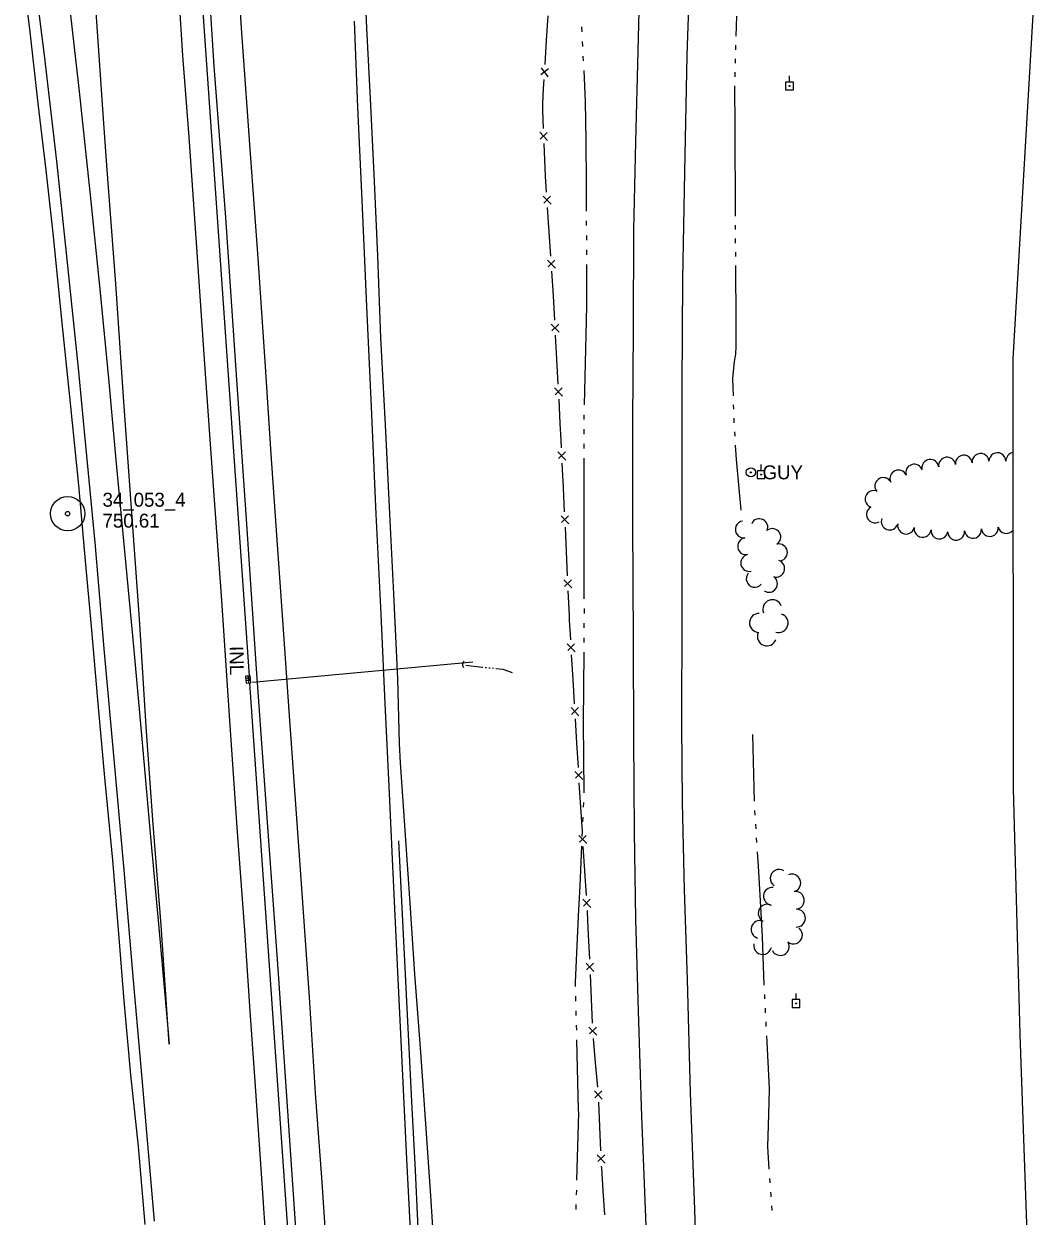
# Model space of a CAD drawing. Extents: x 589250 to 1188077, y 162953 to 363065.
# Drawn here: x 594002 to 594438, y 172738 to 173250 of the extents above; entities that cross this region are included whole.
import ezdxf

# ---------------------------------------------------------------- set-up
doc = ezdxf.new("R2010")
doc.units = 0
for name, color, linetype in [('E_DRN', 7, 'Continuous'), ('E_DRN_Pipe', 7, 'Continuous'), ('E_DRN_SS_UG', 7, 'Continuous'), ('E_DRN_Text', 7, 'Continuous'), ('E_FEN_P', 7, 'Continuous'), ('E_LAND_TreeLine_P', 7, 'Continuous'), ('E_MAP_Limits', 7, 'Continuous'), ('E_MAP_PassPoints', 7, 'Continuous'), ('E_RDWY', 7, 'Continuous'), ('E_RDWY_Gravel', 7, 'Continuous'), ('E_UTL_EGuyWire', 7, 'Continuous'), ('E_UTL_EPowerPole', 7, 'Continuous'), ('E_WAL', 7, 'Continuous'), ('E_WTR_FlowLine', 7, 'Continuous')]:
    doc.layers.add(name, color=color, linetype=linetype)

msp = doc.modelspace()

# ---------------------------------------------------------------- linework, layer by layer
at = {"layer": 'E_DRN'}
for p, q in [((594099.38, 172970.2), (594097.39, 172970.05)), ((594097.39, 172970.05), (594097.61, 172967.06)), ((594099.46, 172969.2), (594097.46, 172969.06)), ((594099.53, 172968.21), (594097.54, 172968.06)), ((594097.61, 172967.06), (594099.6, 172967.21)), ((594098.38, 172970.13), (594098.61, 172967.14)), ((594099.6, 172967.21), (594099.38, 172970.2))]:
    msp.add_line(p, q, dxfattribs=at)
msp.add_arc((594192.42, 172975.03), 1.75, 124.0117, 230.2719, dxfattribs=at)
at = {"layer": 'E_DRN_Pipe'}
msp.add_line((594117.95, 172698.49), (594099.27, 172967.03), dxfattribs=at)
msp.add_lwpolyline([(594163.21, 172899.17), (594166.48, 172833.15), (594167.75, 172807.22), (594168.84, 172784.41), (594170.33, 172757.55), (594171.64, 172729.6), (594173.17, 172701.66), (594174.76, 172674.39), (594177.1, 172640.49), (594178.95, 172611.66), (594181.35, 172577.92), (594185.75, 172513.06), (594188.07, 172482.37), (594189.42, 172460.9)], dxfattribs=at)
at = {"layer": 'E_DRN_SS_UG'}
msp.add_line((594099.21, 172967.94), (594078.59, 173264.28), dxfattribs=at)
msp.add_lwpolyline([(594100.33, 172967.49), (594195.15, 172976.11)], dxfattribs=at)
at = {"layer": 'E_FEN_P'}
for p, q in [((594227.4, 173253.92), (594226.71, 173243.44)), ((594226.71, 173243.44), (594226.02, 173232.95)), ((594227.62, 173231.06), (594224.32, 173228.52)), ((594224.45, 173231.44), (594227.39, 173227.58)), ((594225.35, 173222.69), (594225.14, 173215.97)), ((594225.6, 173226.46), (594225.35, 173222.69)), ((594225.14, 173215.97), (594225.05, 173212.98)), ((594225.05, 173212.98), (594225.36, 173205.47)), ((594223.95, 173203.79), (594227.29, 173200.27)), ((594227.15, 173203.76), (594224.14, 173200.88)), ((594225.63, 173198.97), (594226.06, 173188.47)), ((594226.06, 173188.47), (594226.21, 173184.79)), ((594226.21, 173184.79), (594226.68, 173177.99)), ((594225.32, 173176.27), (594228.75, 173172.84)), ((594228.51, 173176.32), (594225.58, 173173.36)), ((594227.12, 173171.5), (594227.84, 173161.01)), ((594227.84, 173161.01), (594228.55, 173150.53)), ((594227.2, 173148.82), (594230.63, 173145.38)), ((594230.39, 173148.87), (594227.46, 173145.91)), ((594229, 173144.04), (594229.57, 173135.61)), ((594229.57, 173135.61), (594229.68, 173133.56)), ((594229.68, 173133.56), (594230.24, 173123.07)), ((594228.85, 173121.37), (594232.23, 173117.89)), ((594232.04, 173121.37), (594229.07, 173118.46)), ((594230.58, 173116.57), (594231.13, 173106.08)), ((594231.13, 173106.08), (594231.68, 173095.59)), ((594230.3, 173093.89), (594233.67, 173090.41)), ((594233.49, 173093.89), (594230.52, 173090.98)), ((594232.03, 173089.09), (594232.58, 173078.6)), ((594232.58, 173078.6), (594232.96, 173071.4)), ((594232.96, 173071.4), (594233.12, 173068.11)), ((594231.73, 173066.42), (594235.09, 173062.92)), ((594234.92, 173066.41), (594231.93, 173063.51)), ((594233.43, 173061.61), (594233.94, 173051.11)), ((594233.94, 173051.11), (594234.45, 173040.62)), ((594233.06, 173038.93), (594236.42, 173035.43)), ((594236.25, 173038.92), (594233.27, 173036.02)), ((594234.76, 173034.12), (594235.23, 173023.63)), ((594235.23, 173023.63), (594235.7, 173013.13)), ((594234.31, 173011.45), (594237.65, 173007.94)), ((594237.5, 173011.43), (594234.5, 173008.53)), ((594236, 173006.63), (594236.47, 172996.14)), ((594236.47, 172996.14), (594236.56, 172994.02)), ((594236.56, 172994.02), (594237.06, 172985.65)), ((594235.69, 172983.95), (594239.09, 172980.48)), ((594238.88, 172983.97), (594235.93, 172981.03)), ((594237.45, 172979.15), (594238.07, 172968.67)), ((594238.07, 172968.67), (594238.7, 172958.18)), ((594237.33, 172956.48), (594240.73, 172953.01)), ((594240.52, 172956.5), (594237.57, 172953.56)), ((594239.09, 172951.69), (594239.71, 172941.2)), ((594239.71, 172941.2), (594240.34, 172930.71)), ((594238.97, 172929.01), (594242.37, 172925.54)), ((594242.16, 172929.03), (594239.21, 172926.1)), ((594240.73, 172924.22), (594241.39, 172913.73)), ((594241.39, 172913.73), (594242.06, 172903.25)), ((594240.69, 172901.54), (594244.1, 172898.09)), ((594243.88, 172901.57), (594240.94, 172898.63)), ((594242.47, 172896.75), (594243.14, 172886.27)), ((594243.14, 172886.27), (594243.8, 172875.78)), ((594242.43, 172874.08), (594245.85, 172870.63)), ((594245.63, 172874.11), (594242.68, 172871.16)), ((594244.21, 172869.29), (594244.49, 172864.88)), ((594244.49, 172864.88), (594244.76, 172858.8)), ((594244.76, 172858.8), (594245.23, 172848.3)), ((594243.83, 172846.62), (594247.18, 172843.11)), ((594247.02, 172846.6), (594244.03, 172843.71)), ((594245.52, 172841.81), (594245.99, 172831.31)), ((594245.99, 172831.31), (594246.46, 172820.81)), ((594245.06, 172819.13), (594248.41, 172815.62)), ((594248.25, 172819.11), (594245.26, 172816.22)), ((594246.87, 172814.32), (594247.78, 172803.85)), ((594247.78, 172803.85), (594248.68, 172793.39)), ((594247.39, 172791.71), (594250.74, 172788.2)), ((594250.58, 172791.69), (594247.59, 172788.8)), ((594249.08, 172786.9), (594249.56, 172776.4)), ((594249.56, 172776.4), (594250.04, 172765.9)), ((594248.64, 172764.22), (594251.99, 172760.71)), ((594251.83, 172764.2), (594248.84, 172761.31)), ((594250.33, 172759.41), (594250.37, 172758.63)), ((594250.37, 172758.63), (594251.02, 172748.92)), ((594251.02, 172748.92), (594251.73, 172738.44))]:
    msp.add_line(p, q, dxfattribs=at)
at = {"layer": 'E_LAND_TreeLine_P'}
for centre, radius, start, end in [((594391.82, 173059.55), 3.63, 7.4389, 187.4389), ((594399.01, 173060.49), 3.63, 7.4389, 187.4389), ((594406.21, 173061.35), 3.63, 5.9256, 185.9256), ((594413.43, 173062.1), 3.63, 5.9256, 185.9256), ((594420.67, 173062.42), 3.63, 0.9559, 180.9559), ((594427.93, 173062.54), 3.63, 98.8023, 180.9559), ((594378.09, 173054.96), 3.63, 25.1014, 205.1014), ((594384.88, 173057.47), 3.63, 18.0586, 198.0586), ((594371.62, 173051.72), 3.63, 39.1131, 219.1131), ((594367.42, 173046.16), 3.63, 71.7769, 251.7769), ((594368.04, 173039.54), 3.63, 119.0284, 299.0284), ((594318.31, 173034.02), 3.64, 335.1349, 155.1349), ((594374.38, 173036.5), 3.63, 160.1836, 340.1836), ((594311.61, 173033.07), 3.64, 97.7986, 277.7986), ((594323.9, 173029.8), 3.64, 301.9196, 121.9196), ((594381.4, 173034.73), 3.63, 168.5751, 348.5751), ((594388.51, 173033.34), 3.63, 173.9748, 353.9748), ((594395.73, 173032.58), 3.63, 173.9748, 353.9748), ((594402.94, 173032.11), 3.63, 186.3117, 6.3117), ((594410.15, 173032.91), 3.63, 186.3117, 6.3117), ((594417.37, 173033.71), 3.63, 186.3117, 6.3117), ((594424.5, 173034.98), 3.63, 191.495, 322.668), ((594312.6, 173025.85), 3.64, 97.7986, 277.7986), ((594326.73, 173023.21), 3.64, 281.4473, 101.4473), ((594313.97, 173018.7), 3.64, 102.548, 282.548), ((594325.56, 173016.24), 3.64, 250.8606, 70.8606), ((594316.33, 173011.88), 3.64, 139.5322, 319.5322), ((594322.46, 173009.7), 3.64, 235.4182, 55.4182), ((594323.91, 172998.76), 4.1, 21.5119, 201.5119), ((594318.18, 172992.91), 4.1, 88.5699, 268.5699), ((594326.57, 172992.81), 4.1, 252.5209, 72.5209), ((594321.56, 172987.12), 4.1, 159.1545, 339.1545), ((594326.82, 172883.12), 3.83, 57.2658, 237.2658), ((594332.27, 172881.1), 3.83, 291.1807, 111.1807), ((594323.96, 172875.41), 3.83, 84.6157, 264.6157), ((594333.8, 172873.63), 3.83, 277.126, 97.126), ((594321.65, 172868.13), 3.83, 64.3908, 244.3908), ((594334.26, 172866), 3.83, 267.5894, 87.5894), ((594318.61, 172861.1), 3.83, 72.5209, 252.5209), ((594333.01, 172858.7), 3.83, 229.5322, 49.5322), ((594319.74, 172854.2), 3.83, 167.9612, 347.9612), ((594327.29, 172853.81), 3.83, 207.5209, 27.5209)]:
    msp.add_arc(centre, radius, start, end, dxfattribs=at)
at = {"layer": 'E_MAP_Limits'}
for p, q in [((594437.75, 173286.49), (594427.36, 173106.42)), ((594427.36, 173106.42), (594427.43, 172921.65)), ((594427.43, 172921.65), (594430.32, 172816.03)), ((594430.32, 172816.03), (594434.16, 172705.44))]:
    msp.add_line(p, q, dxfattribs=at)
at = {"layer": 'E_MAP_PassPoints'}
for radius in [7.38, 0.945]:
    msp.add_circle((594020.9, 173039.86), radius, dxfattribs=at)
at = {"layer": 'E_RDWY'}
for p, q in [((594036.15, 173211.79), (594031.26, 173284.27)), ((594067.24, 173285.07), (594070.29, 173236.76)), ((594092.99, 173286.81), (594095.67, 173246.58)), ((594266.92, 173274.41), (594266, 173238.71)), ((594288.44, 173276.32), (594287.18, 173237.01)), ((594006.69, 173269.62), (594010.82, 173237.02)), ((594020.8, 173265.6), (594025.84, 173221.3)), ((594144.07, 173251.58), (594145.58, 173214.57)), ((594095.67, 173246.58), (594099.54, 173192.69)), ((594010.82, 173237.02), (594016.11, 173191.44)), ((594266, 173238.71), (594265.03, 173199.63)), ((594287.18, 173237.01), (594286.17, 173186.59)), ((594070.29, 173236.76), (594073.06, 173201.77)), ((594025.84, 173221.3), (594030.41, 173178.19)), ((594037.77, 173189.46), (594036.15, 173211.79)), ((594145.58, 173214.57), (594147.34, 173174.58)), ((594073.06, 173201.77), (594076.39, 173152.1)), ((594265.03, 173199.63), (594264.27, 173161.93)), ((594016.11, 173191.44), (594020.57, 173149.18)), ((594099.54, 173192.69), (594102.61, 173149.74)), ((594041.59, 173138.7), (594037.77, 173189.46)), ((594286.17, 173186.59), (594285.31, 173140.81)), ((594030.41, 173178.19), (594034.88, 173134.95)), ((594147.34, 173174.58), (594149.44, 173128.9)), ((594264.27, 173161.93), (594264.06, 173119.16)), ((594076.39, 173152.1), (594079.88, 173102.12)), ((594102.61, 173149.74), (594105.76, 173103.19)), ((594020.57, 173149.18), (594025.42, 173102.34)), ((594285.31, 173140.81), (594284.93, 173094.57)), ((594034.88, 173134.95), (594038.47, 173097.94)), ((594045.1, 173087.93), (594041.59, 173138.7)), ((594149.44, 173128.9), (594151.37, 173085.77)), ((594264.06, 173119.16), (594263.8, 173079.17)), ((594025.42, 173102.34), (594028.63, 173069.09)), ((594079.88, 173102.12), (594083.34, 173053.7)), ((594105.76, 173103.19), (594108.33, 173065.4)), ((594038.47, 173097.94), (594041.92, 173059.84)), ((594284.93, 173094.57), (594284.97, 173051.34)), ((594048.36, 173042.17), (594045.1, 173087.93)), ((594151.37, 173085.77), (594153.47, 173039.61)), ((594263.8, 173079.17), (594263.83, 173036.17)), ((594028.63, 173069.09), (594032.61, 173027.4)), ((594108.33, 173065.4), (594110.88, 173028.59)), ((594041.92, 173059.84), (594045.52, 173022.22)), ((594083.34, 173053.7), (594087.01, 173002.47)), ((594284.97, 173051.34), (594284.95, 172997.01)), ((594051.81, 172994.69), (594048.36, 173042.17)), ((594153.47, 173039.61), (594155.52, 172996.72)), ((594263.83, 173036.17), (594263.99, 172985.31)), ((594032.61, 173027.4), (594036.68, 172980.24)), ((594110.88, 173028.59), (594113.42, 172992.01)), ((594045.52, 173022.22), (594049.15, 172982.71)), ((594087.01, 173002.47), (594090.53, 172950.92)), ((594155.52, 172996.72), (594157.24, 172958.19)), ((594284.95, 172997.01), (594284.82, 172949.39)), ((594054.73, 172948.4), (594051.81, 172994.69)), ((594113.42, 172992.01), (594116.29, 172950.95)), ((594049.15, 172982.71), (594052.78, 172943.05)), ((594263.99, 172985.31), (594264.23, 172943.24)), ((594036.68, 172980.24), (594040.78, 172934.33)), ((594157.24, 172958.19), (594159.1, 172919.54)), ((594090.53, 172950.92), (594093.64, 172904.99)), ((594116.29, 172950.95), (594119.13, 172910.99)), ((594057.59, 172908.1), (594054.73, 172948.4)), ((594284.82, 172949.39), (594285.15, 172915.64)), ((594052.78, 172943.05), (594056.25, 172904.02)), ((594264.23, 172943.24), (594264.44, 172903.02)), ((594040.78, 172934.33), (594045.02, 172886.55)), ((594159.1, 172919.54), (594160.59, 172888.28)), ((594285.15, 172915.64), (594286, 172878.21)), ((594119.13, 172910.99), (594121.83, 172872.72)), ((594056.25, 172904.02), (594060.45, 172858.74)), ((594061.16, 172862.97), (594057.59, 172908.1)), ((594093.64, 172904.99), (594096.89, 172860.64)), ((594264.44, 172903.02), (594265.05, 172865.58)), ((594160.59, 172888.28), (594162.76, 172842.95)), ((594045.02, 172886.55), (594049.09, 172839.24)), ((594286, 172878.21), (594287.34, 172839.63)), ((594121.83, 172872.72), (594124.69, 172832.02)), ((594064.51, 172811.88), (594061.16, 172862.97)), ((594265.05, 172865.58), (594266.17, 172826.07)), ((594060.45, 172858.74), (594063.93, 172818.6)), ((594096.89, 172860.64), (594099.41, 172823.8)), ((594162.76, 172842.95), (594164.61, 172804.42)), ((594049.09, 172839.24), (594052.77, 172797.07)), ((594287.34, 172839.63), (594288.61, 172790.87)), ((594124.69, 172832.02), (594127.32, 172790.72)), ((594099.41, 172823.8), (594101.25, 172797.87)), ((594266.17, 172826.07), (594267.62, 172780.78)), ((594063.93, 172818.6), (594064.51, 172811.88)), ((594164.61, 172804.42), (594166.65, 172762.38)), ((594052.77, 172797.07), (594058.17, 172735.71)), ((594101.25, 172797.87), (594104.55, 172749.92)), ((594127.32, 172790.72), (594130.19, 172752.45)), ((594288.61, 172790.87), (594290.37, 172740.73)), ((594267.62, 172780.78), (594269.2, 172741.05)), ((594166.65, 172762.38), (594168.81, 172719.74)), ((594104.55, 172749.92), (594108.09, 172696.97)), ((594130.19, 172752.45), (594133.09, 172710.31)), ((594269.2, 172741.05), (594270.86, 172697.39)), ((594290.37, 172740.73), (594292.01, 172698))]:
    msp.add_line(p, q, dxfattribs=at)
at = {"layer": 'E_RDWY_Gravel'}
for p, q in [((594147.81, 173279.58), (594149.47, 173248.5)), ((594002.07, 173267.56), (594004.45, 173248.25)), ((594004.45, 173248.25), (594008.07, 173216.12)), ((594149.47, 173248.5), (594151.05, 173215.41)), ((594008.07, 173216.12), (594011.54, 173187.53)), ((594151.05, 173215.41), (594152.72, 173182.71)), ((594011.54, 173187.53), (594014.61, 173159.21)), ((594152.72, 173182.71), (594154.1, 173150.76)), ((594014.61, 173159.21), (594018.14, 173124.58)), ((594154.1, 173150.76), (594155.4, 173115.51)), ((594018.14, 173124.58), (594022.04, 173087.29)), ((594155.4, 173115.51), (594157.43, 173078.11)), ((594022.04, 173087.29), (594025.53, 173052.11)), ((594157.43, 173078.11), (594159.23, 173039.76)), ((594025.53, 173052.11), (594028.43, 173019.61)), ((594159.23, 173039.76), (594161.03, 173005.46)), ((594028.43, 173019.61), (594031.12, 172989.83)), ((594161.03, 173005.46), (594162.67, 172968.9)), ((594031.12, 172989.83), (594033.83, 172958.24)), ((594162.67, 172968.9), (594163.51, 172941.08)), ((594033.83, 172958.24), (594036.92, 172924.84)), ((594163.51, 172941.08), (594163.84, 172932.8)), ((594163.84, 172932.8), (594165.96, 172901.61)), ((594036.92, 172924.84), (594040.12, 172890.9)), ((594165.96, 172901.61), (594168.01, 172872.49)), ((594040.12, 172890.9), (594042.85, 172857.58)), ((594168.01, 172872.49), (594170.09, 172841.94)), ((594042.85, 172857.58), (594045.08, 172830.37)), ((594170.09, 172841.94), (594172.41, 172810.28)), ((594045.08, 172830.37), (594047.97, 172798.6)), ((594172.41, 172810.28), (594174.87, 172775.62)), ((594047.97, 172798.6), (594051.2, 172767.83)), ((594174.87, 172775.62), (594176.86, 172746.68)), ((594051.2, 172767.83), (594054.07, 172734.33)), ((594176.86, 172746.68), (594179, 172715.65))]:
    msp.add_line(p, q, dxfattribs=at)
at = {"layer": 'E_UTL_EGuyWire'}
for radius in [2, 0.25]:
    msp.add_circle((594314.68, 173057.62), radius, dxfattribs=at)
at = {"layer": 'E_UTL_EPowerPole'}
for points in [[(594331.26, 173225.39), (594331.26, 173228.04)], [(594332.94, 173225.39), (594329.59, 173225.39)], [(594329.59, 173225.39), (594329.59, 173222.04)], [(594329.59, 173222.04), (594332.94, 173222.04)], [(594332.94, 173222.04), (594332.94, 173225.39)], [(594320.7, 173058.34), (594317.35, 173058.34)], [(594317.35, 173058.34), (594317.35, 173054.99)], [(594319.02, 173058.34), (594319.02, 173060.99)], [(594320.7, 173054.99), (594320.7, 173058.34)], [(594317.35, 173054.99), (594320.7, 173054.99)], [(594334.1, 172831), (594334.1, 172833.64)], [(594335.77, 172831), (594332.42, 172831)], [(594332.42, 172831), (594332.42, 172827.64)], [(594332.42, 172827.64), (594335.77, 172827.64)], [(594335.77, 172827.64), (594335.77, 172831)]]:
    msp.add_lwpolyline(points, dxfattribs=at)
for centre in [(594331.29, 173223.72), (594319.05, 173056.67), (594334.13, 172829.32)]:
    msp.add_circle(centre, 0.217, dxfattribs=at)
at = {"layer": 'E_WAL'}
for p, q in [((594080.62, 173281.68), (594083.71, 173232.18)), ((594083.71, 173232.18), (594088.77, 173167.18)), ((594088.77, 173167.18), (594093.33, 173099.48)), ((594093.33, 173099.48), (594097.6, 173037.43)), ((594097.6, 173037.43), (594102, 172973.15)), ((594102, 172973.15), (594107, 172903.25)), ((594107, 172903.25), (594111.25, 172844.18)), ((594111.25, 172844.18), (594116.59, 172766.21)), ((594116.59, 172766.21), (594121.38, 172696.7))]:
    msp.add_line(p, q, dxfattribs=at)
at = {"layer": 'E_WTR_FlowLine'}
for p, q in [((594308.45, 173253.65), (594308.21, 173245.08)), ((594241.85, 173249.07), (594241.96, 173246.99)), ((594242.16, 173242.82), (594242.27, 173240.74)), ((594308.11, 173241.22), (594308.05, 173239.29)), ((594242.48, 173236.58), (594242.58, 173234.5)), ((594307.95, 173235.42), (594307.9, 173233.49)), ((594242.79, 173230.34), (594243.46, 173217.07)), ((594307.79, 173229.63), (594307.74, 173227.69)), ((594307.69, 173223.83), (594307.8, 173206)), ((594243.46, 173217.07), (594243.64, 173200.14)), ((594307.8, 173206), (594307.81, 173195.8)), ((594243.64, 173200.14), (594243.83, 173181.76)), ((594307.81, 173195.8), (594307.84, 173178.57)), ((594243.83, 173181.76), (594243.87, 173169.92)), ((594307.84, 173178.57), (594307.9, 173167.77)), ((594243.89, 173165.75), (594243.9, 173163.67)), ((594307.93, 173163.9), (594307.94, 173161.97)), ((594243.92, 173159.5), (594243.92, 173157.42)), ((594307.96, 173158.1), (594307.97, 173156.17)), ((594243.94, 173153.25), (594243.95, 173151.17)), ((594307.99, 173152.3), (594308, 173150.37)), ((594243.97, 173147), (594244.04, 173129.13)), ((594308.04, 173146.5), (594308.26, 173122.37)), ((594244.04, 173129.13), (594243.72, 173116.79)), ((594308.26, 173122.37), (594308.25, 173118.47)), ((594243.72, 173116.79), (594242.93, 173086.58)), ((594308.25, 173118.47), (594308.23, 173111.86)), ((594308.23, 173111.86), (594308.08, 173108.45)), ((594307.52, 173105.24), (594306.82, 173097.91)), ((594308.08, 173108.45), (594307.52, 173105.24)), ((594306.82, 173097.91), (594306.99, 173090.53)), ((594307.08, 173086.66), (594307.13, 173084.73)), ((594242.82, 173082.41), (594242.82, 173080.33)), ((594307.29, 173080.87), (594307.4, 173078.94)), ((594242.82, 173076.16), (594242.81, 173074.08)), ((594307.63, 173075.08), (594307.74, 173073.15)), ((594242.81, 173069.91), (594242.81, 173067.83)), ((594307.97, 173069.29), (594308.32, 173063.18)), ((594242.81, 173063.66), (594242.8, 173043.37)), ((594308.32, 173063.18), (594310.3, 173041.36)), ((594242.8, 173043.37), (594242.83, 173033.44)), ((594242.83, 173033.44), (594242.91, 173003.22)), ((594242.92, 172999.06), (594242.92, 172996.97)), ((594242.9, 172992.81), (594242.89, 172990.72)), ((594242.86, 172986.55), (594242.84, 172984.47)), ((594242.81, 172980.3), (594242.59, 172950.09)), ((594192.17, 172974.7), (594199.2, 172973.85)), ((594199.2, 172973.85), (594199.47, 172973.82)), ((594200.48, 172973.73), (594200.98, 172973.68)), ((594201.99, 172973.58), (594202.5, 172973.54)), ((594203.51, 172973.44), (594204.01, 172973.39)), ((594205.02, 172973.3), (594207.98, 172973.02)), ((594207.98, 172973.02), (594212.1, 172971.53)), ((594242.59, 172950.08), (594242.59, 172949.86)), ((594242.59, 172949.86), (594242.86, 172920.33)), ((594315.34, 172944.95), (594316.11, 172916.26)), ((594242.86, 172920.33), (594242.84, 172919.87)), ((594242.66, 172915.71), (594242.56, 172913.63)), ((594242.38, 172909.46), (594242.29, 172907.38)), ((594316.29, 172912.3), (594316.41, 172910.32)), ((594316.65, 172906.37), (594316.76, 172904.4)), ((594242.11, 172903.22), (594242.02, 172901.13)), ((594317, 172900.44), (594317.12, 172898.47)), ((594241.84, 172896.97), (594241.09, 172879.88)), ((594317.36, 172894.51), (594317.73, 172888.28)), ((594317.73, 172888.28), (594319.1, 172865.86)), ((594241.09, 172879.88), (594240.47, 172866.79)), ((594240.47, 172866.79), (594239.12, 172838.31)), ((594319.1, 172865.86), (594319.58, 172857.99)), ((594319.58, 172857.99), (594320.3, 172837.18)), ((594239.12, 172838.31), (594239.16, 172836.61)), ((594239.26, 172832.44), (594239.31, 172830.36)), ((594320.46, 172833.22), (594320.56, 172831.25)), ((594320.75, 172827.29), (594320.84, 172825.31)), ((594239.42, 172826.19), (594239.47, 172824.11)), ((594239.57, 172819.94), (594239.62, 172817.86)), ((594321.04, 172821.36), (594321.13, 172819.38)), ((594239.72, 172813.69), (594240.47, 172783.49)), ((594321.32, 172815.43), (594322.52, 172792.76)), ((594322.52, 172792.76), (594322.39, 172786.75)), ((594322.39, 172786.75), (594322.17, 172776.88)), ((594240.5, 172782.36), (594239.74, 172753.28)), ((594240.47, 172783.48), (594240.5, 172782.36)), ((594322.17, 172776.88), (594321.8, 172767.8)), ((594321.8, 172767.8), (594322.45, 172758.08)), ((594322.71, 172754.13), (594322.84, 172752.15)), ((594239.63, 172749.11), (594239.57, 172747.03)), ((594323.11, 172748.2), (594323.18, 172747.09)), ((594323.18, 172747.09), (594323.24, 172746.22)), ((594239.47, 172742.86), (594239.41, 172740.81)), ((594239.41, 172740.81), (594239.41, 172740.78)), ((594323.52, 172742.27), (594323.65, 172740.3))]:
    msp.add_line(p, q, dxfattribs=at)

# ---------------------------------------------------------------- texts
at = {"layer": 'E_DRN_Text'}
msp.add_text('INL', height=6, rotation=270.9559, dxfattribs=at).set_placement((594090.49, 172982.91))
at = {"layer": 'E_MAP_PassPoints'}
for s, p in [('34_053_4', (594035.9, 173042.85)), ('750.61', (594035.9, 173033.85))]:
    msp.add_text(s, height=6, dxfattribs=at).set_placement(p)
at = {"layer": 'E_UTL_EGuyWire'}
msp.add_text('GUY', height=6, dxfattribs=at).set_placement((594319.68, 173054.62))

doc.saveas('drawing.dxf')
